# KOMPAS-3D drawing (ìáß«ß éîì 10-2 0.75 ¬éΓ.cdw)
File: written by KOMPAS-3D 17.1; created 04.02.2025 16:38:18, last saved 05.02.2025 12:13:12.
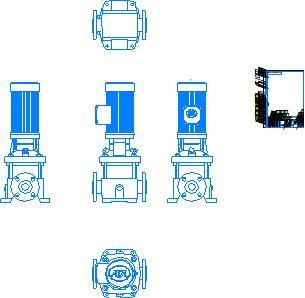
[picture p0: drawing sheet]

Sheet 1: A4, portrait

Title block, sheet 1: name: Насос ВМН 10-2 / 0.75 кВт; designation: Насос ВМН 10-2 0.75 кВт; material: Сталь 10  ГОСТ 1050-2013; mass: 222,7; sheets: 1; sheet format: A4; stored path: \\adlc.lan\data\АДЛ_ПКД\3D-модели\ADL production\Насосы ГРАНПАМП\Насосы ВМН\ВМН10\KOMPAS 3D\Насос ВМН 10-2 0.75 кВт.cdw

Views: Проекционный вид 2, Проекционный вид 3, Проекционный вид 4, Проекционный вид 5
Referenced files in \\adlc.lan\data\АДЛ_ПКД\3D-модели\ADL production\Насосы ГРАНПАМП\Насосы ВМН\ВМН10\KOMPAS 3D\: ВМН 10-2 0,75 кВт.m3d, Насос ВМН 10-2 0,75 кВт.m3d
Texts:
  Andrey
  АДЛ
Dimensions and other numbers on the sheet: 1:1; 1; 0.75 кВт; 222,7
